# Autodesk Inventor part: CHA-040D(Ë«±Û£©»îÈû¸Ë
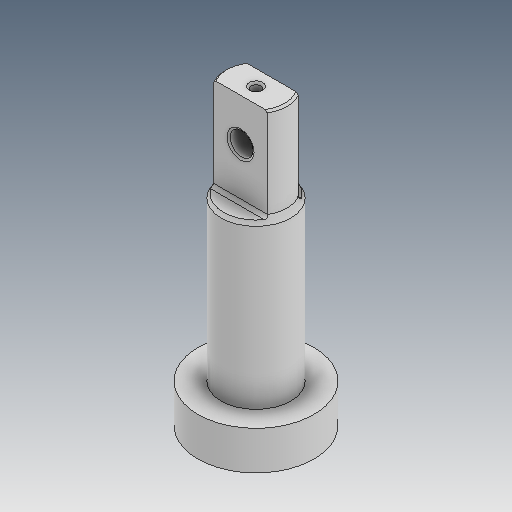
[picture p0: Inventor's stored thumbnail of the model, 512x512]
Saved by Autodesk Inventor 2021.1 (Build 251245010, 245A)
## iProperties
Created: 2019-12
Part Number: CHA-040D(Ë«±Û£©»îÈû¸Ë
Material: Ogólny
Document SubType Name: Modeling
Designer: user
Density: 1 g/cm^3
Appearance: Domyślna
Author: user
Revision Number: ÈÎºÎ
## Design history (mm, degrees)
feature "ÊäÈë1"
node "Bryła1"
